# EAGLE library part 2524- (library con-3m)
3M (TM) Pak 100 4-Wall Header Source: 3M
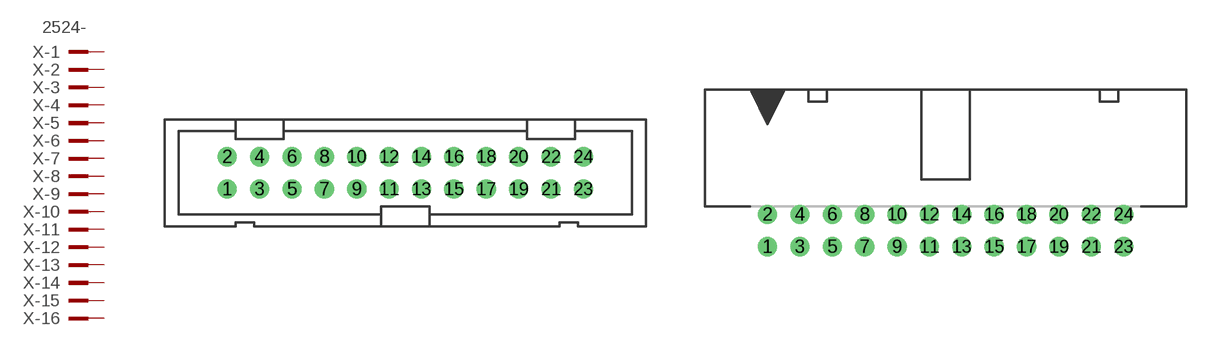
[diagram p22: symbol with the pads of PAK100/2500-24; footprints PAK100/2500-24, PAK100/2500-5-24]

Designator prefix X; gates -1=PINV -2=PIN -3=PIN -4=PIN -5=PIN -6=PIN -7=PIN -8=PIN -9=PIN -10=PIN -11=PIN -12=PIN -13=PIN -14=PIN -15=PIN -16=PIN -17=PIN -18=PIN -19=PIN -20=PIN -21=PIN -22=PIN -23=PIN -24=PIN

## 2524- (OC_FARNELL: unknown; OC_NEWARK: unknown)  [PAK100/2500-24]
1  -1:KL  pas
2  -2:KL  pas
3  -3:KL  pas
4  -4:KL  pas
5  -5:KL  pas
6  -6:KL  pas
7  -7:KL  pas
8  -8:KL  pas
9  -9:KL  pas
10  -10:KL  pas
11  -11:KL  pas
12  -12:KL  pas
13  -13:KL  pas
14  -14:KL  pas
15  -15:KL  pas
16  -16:KL  pas
17  -17:KL  pas
18  -18:KL  pas
19  -19:KL  pas
20  -20:KL  pas
21  -21:KL  pas
22  -22:KL  pas
23  -23:KL  pas
24  -24:KL  pas

## 2524-5 (OC_FARNELL: 9838465; OC_NEWARK: unknown)  [PAK100/2500-5-24]
Pads as for PAK100/2500-24

## Footprint PAK100/2500-24 (pad centres in mm)
3M (TM) Pak 100 4-Wall Header Straight Source: 3M
drill 1 pad 1.422 round: 1 -13.97,-1.27; 2 -13.97,1.27; 3 -11.43,-1.27; 4 -11.43,1.27; 5 -8.89,-1.27; 6 -8.89,1.27; 7 -6.35,-1.27; 8 -6.35,1.27; 9 -3.81,-1.27; 10 -3.81,1.27; 11 -1.27,-1.27; 12 -1.27,1.27; 13 1.27,-1.27; 14 1.27,1.27; 15 3.81,-1.27; 16 3.81,1.27; 17 6.35,-1.27; 18 6.35,1.27; 19 8.89,-1.27; 20 8.89,1.27; 21 11.43,-1.27; 22 11.43,1.27; 23 13.97,-1.27; 24 13.97,1.27

## Footprint PAK100/2500-5-24 (pad centres in mm)
3M (TM) Pak 100 4-Wall Header Right Angle Source: 3M
drill 1 pad 1.422 round: 1 -13.97,-1.27; 2 -13.97,1.27; 3 -11.43,-1.27; 4 -11.43,1.27; 5 -8.89,-1.27; 6 -8.89,1.27; 7 -6.35,-1.27; 8 -6.35,1.27; 9 -3.81,-1.27; 10 -3.81,1.27; 11 -1.27,-1.27; 12 -1.27,1.27; 13 1.27,-1.27; 14 1.27,1.27; 15 3.81,-1.27; 16 3.81,1.27; 17 6.35,-1.27; 18 6.35,1.27; 19 8.89,-1.27; 20 8.89,1.27; 21 11.43,-1.27; 22 11.43,1.27; 23 13.97,-1.27; 24 13.97,1.27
